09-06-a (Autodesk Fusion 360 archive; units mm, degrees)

design "09-06-a" references "09-PIN", "09-KADOU", "09-KOTEI"
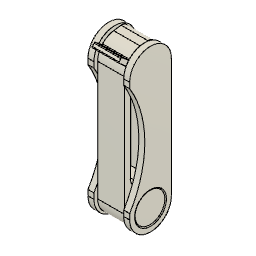
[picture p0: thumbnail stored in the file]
component_insert "コンポーネントの挿入1" AlongDistance -7
ground "固定"
component_insert "コンポーネントの挿入2"
joint "アセンブリ1" alignAngle 0 alignOffsetX 0 alignOffsetY 0 alignOffsetZ 0
component_insert "コンポーネントの挿入3"
joint "アセンブリ2" alignAngle 0 alignOffsetX 0 alignOffsetY 0 alignOffsetZ 0
component_insert "コンポーネントの挿入4"
joint "アセンブリ4" alignAngle 0 alignOffsetX 0 alignOffsetY 0 alignOffsetZ 0

design "09-KADOU"
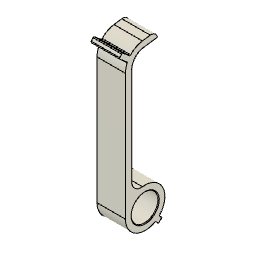
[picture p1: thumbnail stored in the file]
sketch "スケッチ1" plane through (0, 0, 0) normal (1, 0, 0) x axis (0, 0, -1)
  circle C1 centre (0, 0) radius 6.25
  point P1 (0, 0)
  point P2 (0, 0)
  coincident P1 P2
  dimension "d1" diameter C1 = 12.5
extrude "押し出し1" new body sketch "スケッチ1" distance 9
sketch "スケッチ2" plane through (0, 0, 0) normal (1, 0, 0) x axis (0, 0, -1)
  line L1 (-4.25, 0) -> (-4.25, 40)
  line L2 (-6.25, 0) -> (-4.25, 0)
  line L3 (-6.25, 40) -> (-6.25, 0)
  line L4 (3.8647, 44.8349) -> (-0.5915, 44.2086)
  line L5 (3.5864, 46.8155) -> (3.8647, 44.8349)
  line L6 (-0.8698, 46.1892) -> (3.5864, 46.8155)
  circle C1 centre (0, 0) radius 6.25
  arc A1 centre (0, 40) radius 4.25 clockwise from (-4.25, 40) to (-0.5915, 44.2086)
  arc A2 centre (0, 40) radius 6.25 clockwise from (-6.25, 40) to (-0.8698, 46.1892)
  point P1 (0, 0)
  point P8 (0, 40)
  point P12 (0, 40)
  vertical L1
  horizontal L2
  vertical L3
  coincident P1 L2
  tangent L3 C1
  perpendicular L4 L5
  perpendicular L5 L6
  coincident P8 P12
  vertical P1 P8
  tangent L1 A1
  tangent A1 L4
  tangent L3 A2
  dimension "d5" distance L1 L3 = 2
  dimension "d18" distance L4 L6 = 2
  dimension "d21" distance P8 L5 = 4.5
  dimension "d22" angle L1 L4 = 98
  dimension "d54" distance P1 P12 = 40
extrude "押し出し2" add sketch "スケッチ2" profile of L1 L3 C1 distance 9
sketch "スケッチ4" plane through (0, 0, 0) normal (1, 0, 0) x axis (0, 0, -1)
  line L1 (5.3033, -5.3033) -> (0, 0)
  line L2 (4.2426, -6.364) -> (5.3033, -5.3033)
  line L3 (-1.0607, -1.0607) -> (4.2426, -6.364)
  line L4 (0, 0) -> (-1.0607, -1.0607)
  line L5 (-22.5, 0) -> (-1.75, 0)
  point P1 (0, 0)
  point P2 (0, 0)
  perpendicular L1 L2
  parallel L1 L3
  parallel L2 L4
  coincident P1 P2
  dimension "d24" angle L1 L5 = 45
  dimension "d25" distance L2 L4 = 7.5
  dimension "d26" distance L1 L3 = 1.5
extrude "押し出し4" add sketch "スケッチ4" profile of L1 L2 L3 L4 distance 9
joint_origin "JointOrigin1" OffsetX 0 OffsetY 0 OffsetZ 0 AngleZ 0
sketch "スケッチ5" plane through (0, 0, 0) normal (1, 0, 0) x axis (0, 0, -1)
  line L1 (0, 40) -> (-7.2774, 46.1065)
  line L2 (-0.9642, 38.8509) -> (0, 40)
  line L3 (-8.2416, 44.9574) -> (-0.9642, 38.8509)
  line L4 (-7.2774, 46.1065) -> (-8.2416, 44.9574)
  line L5 (0, 22.5) -> (0, 1.75)
  arc A1 centre (0, 40) radius 4.25 clockwise from (-4.25, 40) to (-0.5915, 44.2086)
  point P3 (0, 40)
  point P8 (0, 40)
  perpendicular L1 L2
  parallel L1 L3
  parallel L2 L4
  coincident P3 P8
  dimension "d33" angle L1 L5 = 50
  dimension "d34" distance L1 L3 = 1.5
  dimension "d35" distance L2 L4 = 9.5
extrude "押し出し5" add sketch "スケッチ5" profile of L1 L3 L4 A1 distance 9
fillet "フィレット3" radius 2
sketch "スケッチ6" plane through (0, 43.4339, 6.1042) normal (0, -0.9903, -0.1392) x axis (-1, 0, 0)
  line L1 (-4.5, 10.0669) -> (4.5, 10.0669)
  line L2 (-4.5, 5.5669) -> (-4.5, 10.0669)
  line L3 (4.5, 5.5669) -> (-4.5, 5.5669)
  line L4 (4.5, 10.0669) -> (4.5, 5.5669)
  circle C1 centre (0, 8.0669) radius 0.75
  point P1 (0, 0)
  point P6 (0, 8.0669)
  vertical P1 P6
  dimension "d40" distance L1 P6 = 2
  dimension "d41" diameter C1 = 1.5
extrude "押し出し6" add sketch "スケッチ6" profile of C1 along normal blind 0.7
fillet "フィレット4" radius 0.6
fillet "フィレット5" radius 3
fillet "フィレット6" radius 0.3
hole "穴" HoleDepth 9 HoleDiameter 8.5 TipAngle 118
chamfer "面取り" distance 0.2

design "09-PIN"
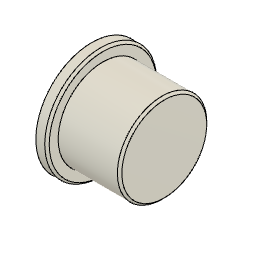
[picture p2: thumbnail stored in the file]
sketch "スケッチ" plane through (0, 0, 0) normal (0, 0, 1) x axis (1, 0, 0)
  line L1 (0, 5) -> (0, 0)
  line L2 (1, 5) -> (0, 5)
  line L3 (1, 4) -> (1, 5)
  line L4 (6.5, 4) -> (1, 4)
  line L5 (6.5, 0) -> (6.5, 4)
  line L6 (0, 0) -> (6.5, 0)
  point P1 (0, 0)
  point P2 (0, 0)
  point P8 (0, 0)
  point P3 (0, 5)
  point P4 (1, 5)
  point P5 (1, 4)
  point P6 (6.5, 4)
  coincident P1 P2
  vertical L1
  perpendicular L1 L2
  perpendicular L2 L3
  perpendicular L3 L4
  perpendicular L4 L5
  coincident P1 P8
  horizontal L6
  dimension "d1" = 8
  dimension "d2" = 10
  dimension "d3" distance P3 P4 = 1
  dimension "d4" distance P5 P6 = 5.5
revolve "回転" sketch "スケッチ" AlongAngle 360
chamfer "面取り" distance 0.2

design "09-KOTEI"
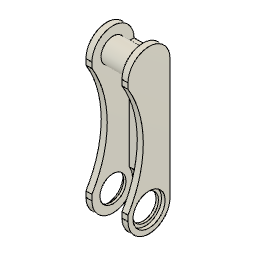
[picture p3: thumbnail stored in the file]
sketch "スケッチ1" plane through (0, 0, 0) normal (1, 0, 0) x axis (0, 0, -1)
  circle C1 centre (0, 40) radius 4
  point P1 (0, 0)
  point P2 (0, 40)
  vertical P1 P2
  dimension "d1" diameter C1 = 8
  dimension "d29" distance P1 P2 = 40
extrude "押し出し1" new body sketch "スケッチ1" + "スケッチ5" profile of S1:C1 distance 10
sketch "スケッチ2" plane through (5, 0, 0) normal (1, 0, 0) x axis (0, 0, -1)
  line L1 (-7, 0) -> (-7, 40)
  line L2 (7, 40) -> (7, 0)
  line L3 (0, 0) -> (0, 40)
  circle C1 centre (0, 40) radius 4
  arc A1 centre (0, 0) radius 7 clockwise from (7, 0) to (-7, 0)
  arc A2 centre (0, 40) radius 7 clockwise from (-7, 40) to (7, 40)
  point P7 (0, 40)
  point P9 (0, 40)
  point P8 (0, 0)
  tangent L1 A1
  tangent A1 L2
  parallel L1 L2
  tangent L2 A2
  tangent L1 A2
  vertical L3
  coincident P7 P9
  concentric C1 A2
  dimension "d4" radius A2 = 7
  dimension "d5" distance P7 P8 = 40
extrude "押し出し2" add sketch "スケッチ2" profile of C1 L1 A1 L2 A2 along normal blind 2
mirror "ミラー" sketch "スケッチ5" mirrorStitchTolerance 0.1
sketch "スケッチ3" plane through (0, 0, 0) normal (1, 0, 0) x axis (0, 0, -1)
  line L1 (7, 40) -> (5.4, 40)
  line L2 (7, 0) -> (7, 40)
  line L3 (5.4, 0) -> (7, 0)
  line L4 (5.4, 40) -> (5.4, 0)
  point P3 (7, 40)
  point P6 (7, 40)
  point P4 (7, 0)
  point P7 (7, 0)
  horizontal L1
  vertical L2
  horizontal L3
  vertical L4
  coincident P3 P6
  coincident P4 P7
  dimension "d10" distance L2 L4 = 1.6
extrude "押し出し3" add sketch "スケッチ3" distance 10
sketch "スケッチ4" plane through (0, 0, 0) normal (1, 0, 0) x axis (0, 0, -1)
  circle C1 centre (-36.9324, 20) radius 35
  arc A1 centre (0, 40) radius 7 clockwise from (-7, 40) to (7, 40)
  arc A2 centre (0, 0) radius 7 clockwise from (7, 0) to (-7, 0)
  tangent C1 A1
  tangent C1 A2
  dimension "d13" diameter C1 = 70
extrude "押し出し4" cut sketch "スケッチ4" profile of C1 no distance stored
sketch "スケッチ5" plane through (0, 0, 0) normal (1, 0, 0) x axis (0, 0, -1)
  circle C1 centre (0, 0) radius 6.5
  arc A1 centre (0, 0) radius 7 clockwise from (7, 0) to (-7, 0)
  concentric C1 A1
  dimension "d15" diameter C1 = 13
extrude "押し出し5" cut sketch "スケッチ5" profile of C1 distance 10
chamfer "面取り" distance 0.2
hole "穴1" HoleDepth 2 HoleDiameter 8.7 TipAngle 118 CBDepth 1.2 CBDiameter 10.7
hole "穴2" HoleDepth 2 HoleDiameter 8.7 TipAngle 118 CBDepth 1.2 CBDiameter 10.7
joint_origin "JointOrigin1" sketch "スケッチ5" OffsetX 0 OffsetY 0 OffsetZ 0 AngleZ 0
